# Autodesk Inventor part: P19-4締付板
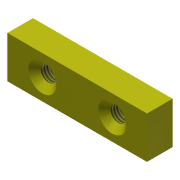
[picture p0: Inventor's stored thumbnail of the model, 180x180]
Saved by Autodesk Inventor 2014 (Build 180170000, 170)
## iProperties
Created: 2008-07
Part Number: P19-4締付板
Document SubType Name: Modeling
Designer: y-shimohigashi
Density: 1 g/cm^3
Stock Number: P19-4締付板
Material: 一般
Appearance: 黄
Author: y-shimohigashi
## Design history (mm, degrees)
sketch "スケッチ1"
  geometry: L1 (-30, 5.5)-(30, 5.5); L2 (30, 5.5)-(30, -5.5); L3 (30, -5.5)-(-30, -5.5); L4 (-30, -5.5)-(-30, 5.5); L5 (30, 5.5)-(-30, -5.5); 2 further points
  constraints: 10 end point, 2 parallel, 1 coincident, 1 horizontal, 1 midpoint, 1 perpendicular
  dimensions: "d0" = 11 distance of L1.end L2.end; "d1" = 60 distance of L2.end L3.end
extrude "押し出し1" new body sketch "スケッチ1" distance "d2" = 18; taper "d3" = 0 deg
sketch "スケッチ2"
  geometry: L1 (30, -3.6)-(30, 21.6) reference; L2 (60, 0)-(60, 18) reference; 3 further points
  constraints: 1 horizontal alignment, 1 midpoint, 1 symmetric about line
  dimensions: "d4" = 30 distance of point (45, 9) point (15, 9)
hole "穴1" sketch "スケッチ2" at (15, 9), (45, 9) diameter "d5" = 6.647; stored, may be unused: countersink angle "d9" = 90 deg, drill point angle "d11" = 118 deg; dims "d6" = 6, "d7" = 12, "d8" = 2, "d10" = 8
node "ソリッド1"
node "ソリッド ボディ"
node "サーフェス ボディ"
